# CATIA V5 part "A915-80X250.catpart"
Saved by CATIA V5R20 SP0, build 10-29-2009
Part number: A915-80X250
Source: Unknown
Property "A": "0.000"
Property "ARTICLENO": "A915-80X250"
Property "BOMINFO": "A915-80X250"
Property "CODE": "A915-80X250"
Property "CREATOR": "CADENAS GmbH"
Property "D": "13.500"
Property "D1": "20.000"
Property "FORM": "B"
Property "L": "250.000"
Property "L1": "40.000"
Property "L2": "170.000"
Property "LINA": "A915-80X250"
Property "NB": "A915-80X250"
Property "NBSYN": "$CODE."
Property "NN": "A915"
Property "NT": "VDI 3357 Wear Plates, steel"
Property "SCREW": "M12x25"
Property "SUPPLIER": "CF"
Property "T": "13.000"
Property "W": "80.000"
Bounding box of the stored display mesh (mm): x 0 to 20, y 0 to 250, z -40 to 40
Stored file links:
  C:\Users\borellobunino\Desktop\3D X SITO CF\A915\GSB_OILLESS_G22501080250\CATIAV5\A915-80X250.catpart
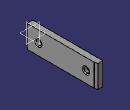
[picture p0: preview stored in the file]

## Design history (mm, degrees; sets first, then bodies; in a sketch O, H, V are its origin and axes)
Body1 "Geometry.1" (main body)
  Solid1 "A915-80X250.catpart": solid without history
